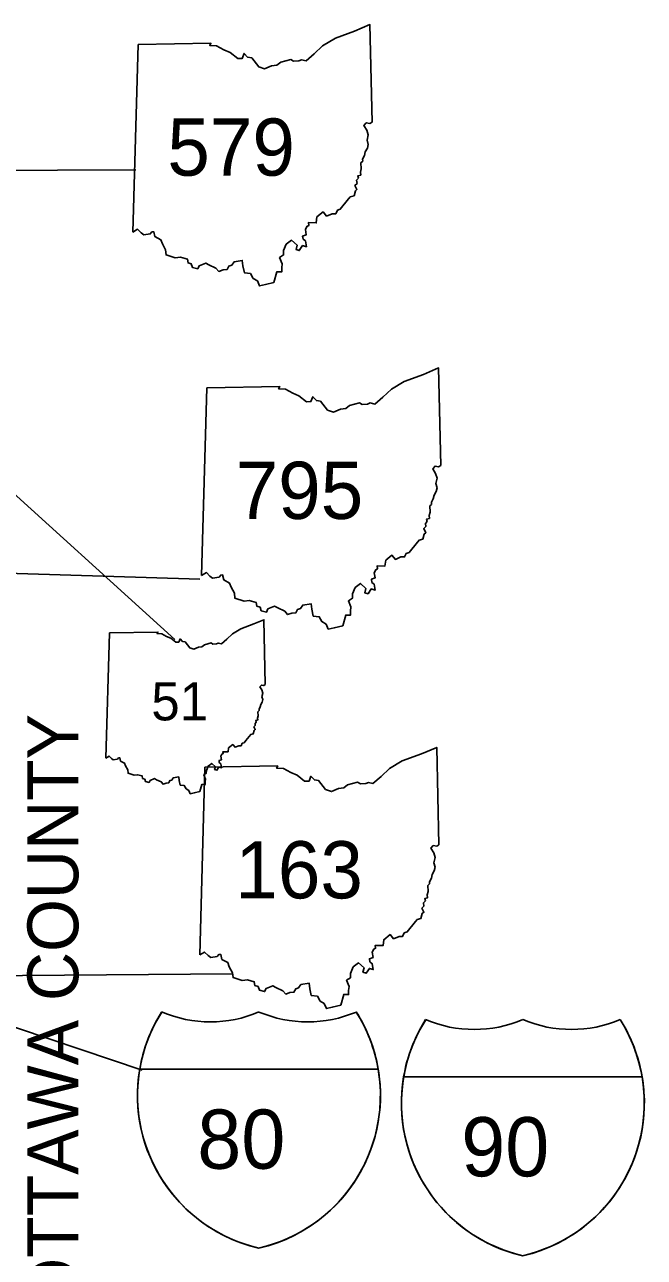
# Model space of a CAD drawing. Extents: x 0 to 851, y 0 to 440.
# Drawn here: x 425.3 to 466.1, y 277.3 to 358.6 of the extents above; entities that cross this region are included whole.
import ezdxf

# ---------------------------------------------------------------- set-up
doc = ezdxf.new("R2010")
doc.units = 0
for name, color, linetype in [('GM_X_Adjacent_County_Text', 7, 'Continuous'), ('GM_X_Interstate_Route', 7, 'Continuous'), ('GM_X_State_Route', 7, 'Continuous'), ('PV_P_Text', 7, 'Continuous')]:
    doc.layers.add(name, color=color, linetype=linetype)

msp = doc.modelspace()

# ---------------------------------------------------------------- linework, layer by layer
at = {"layer": 'GM_X_Interstate_Route'}
msp.add_lwpolyline([(422.811, 293.104), (433.003, 289.671)], dxfattribs=at)
at = {"layer": 'GM_X_State_Route'}
for points in [[(405.522, 348.977), (410.58, 348.972), (411.303, 348.959), (411.878, 348.96), (413.295, 348.968), (414.081, 348.964), (414.459, 348.972), (414.805, 348.979), (415.504, 348.964), (416.351, 348.962), (416.522, 348.963), (417.074, 348.966), (417.881, 348.962), (418.577, 348.966), (418.918, 348.962), (419.177, 348.959), (419.946, 348.952), (420.653, 348.95), (421.433, 348.96), (422.23, 348.953), (432.582, 349.009)], [(435.156, 318.06), (422.587, 329.422)], [(414.918, 322.727), (415.001, 322.725), (416.011, 322.704), (416.997, 322.68), (417.837, 322.648), (418.91, 322.624), (419.627, 322.596), (420.185, 322.567), (420.787, 322.544), (421.903, 322.491), (436.8, 322.031)], [(418.043, 295.878), (419.56, 295.875), (438.954, 296.017)]]:
    msp.add_lwpolyline(points, dxfattribs=at)
at = {"layer": 'PV_P_Text'}
for p, q in [((432.38, 344.897), (432.726, 357.27)), ((432.38, 344.897), (432.726, 357.27)), ((436.912, 322.277), (437.259, 334.649)), ((436.912, 322.277), (437.259, 334.649)), ((430.601, 310.244), (430.832, 318.493)), ((430.601, 310.244), (430.832, 318.493)), ((436.787, 297.273), (437.134, 309.645)), ((436.787, 297.273), (437.134, 309.645)), ((432.835, 289.738), (448.551, 289.738)), ((448.551, 289.738), (432.835, 289.738)), ((448.551, 289.738), (432.835, 289.738)), ((450.229, 289.236), (465.944, 289.236)), ((465.944, 289.236), (450.229, 289.236)), ((465.944, 289.236), (450.229, 289.236))]:
    msp.add_line(p, q, dxfattribs=at)
for points in [[(432.726, 357.27), (437.526, 357.351), (437.451, 357.201), (437.904, 357.17), (438.385, 356.905), (438.792, 356.738), (439.29, 356.345), (439.588, 356.349), (439.714, 356.672), (439.942, 356.423), (440.213, 356.379), (440.681, 355.786), (441.067, 355.658), (441.53, 355.861), (441.876, 355.894), (442.128, 356.095), (442.787, 356.267), (442.971, 356.164), (443.319, 356.185), (443.495, 356.26), (443.799, 356.193), (444.335, 356.642), (444.886, 357.173), (445.734, 357.673), (447, 358.148), (448.001, 358.572), (448.146, 352.151)], [(432.726, 357.27), (437.526, 357.351), (437.451, 357.201), (437.904, 357.17), (438.385, 356.905), (438.792, 356.738), (439.29, 356.345), (439.588, 356.349), (439.714, 356.672), (439.942, 356.423), (440.213, 356.379), (440.681, 355.786), (441.067, 355.658), (441.53, 355.861), (441.876, 355.894), (442.128, 356.095), (442.787, 356.267), (442.971, 356.164), (443.319, 356.185), (443.495, 356.26), (443.799, 356.193), (444.335, 356.642), (444.886, 357.173), (445.734, 357.673), (447, 358.148), (448.001, 358.572), (448.146, 352.151)], [(448.146, 352.151), (447.998, 352.061), (447.768, 352.103), (447.613, 351.923), (447.805, 351.623), (447.895, 351.305), (447.815, 350.956), (447.894, 350.667), (447.84, 350.425), (447.696, 350.185), (447.646, 349.956), (447.523, 349.714), (447.533, 349.579), (447.416, 349.472), (447.437, 349.071), (447.378, 348.848), (447.398, 348.656), (447.208, 348.606), (447.252, 348.447), (447.131, 348.325), (447.157, 348.114), (447.02, 347.98), (447.153, 347.71), (447.046, 347.625), (446.957, 347.297), (446.713, 347.231), (446.225, 346.631), (446.053, 346.405), (445.859, 346.349), (445.753, 346.116), (445.515, 346.115), (445.154, 345.954), (444.921, 346.231), (444.512, 345.897), (444.465, 345.512), (443.949, 345.524), (443.969, 345.329), (443.854, 345.272), (443.749, 345.077), (443.81, 344.729), (443.568, 344.641), (443.597, 344.439), (443.752, 344.316), (443.821, 343.931), (443.564, 344.009), (443.353, 343.684), (443.137, 343.76), (443.208, 344.035), (442.842, 344.366), (442.496, 344.101), (442.316, 343.678), (442.314, 343.393), (442.056, 343.221), (442.221, 342.819), (442.191, 342.541), (442.196, 342.278), (441.874, 342.288), (441.679, 341.577)], [(448.146, 352.151), (447.998, 352.061), (447.768, 352.103), (447.613, 351.923), (447.805, 351.623), (447.895, 351.305), (447.815, 350.956), (447.894, 350.667), (447.84, 350.425), (447.696, 350.185), (447.646, 349.956), (447.523, 349.714), (447.533, 349.579), (447.416, 349.472), (447.437, 349.071), (447.378, 348.848), (447.398, 348.656), (447.208, 348.606), (447.252, 348.447), (447.131, 348.325), (447.157, 348.114), (447.02, 347.98), (447.153, 347.71), (447.046, 347.625), (446.957, 347.297), (446.713, 347.231), (446.225, 346.631), (446.053, 346.405), (445.859, 346.349), (445.753, 346.116), (445.515, 346.115), (445.154, 345.954), (444.921, 346.231), (444.512, 345.897), (444.465, 345.512), (443.949, 345.524), (443.969, 345.329), (443.854, 345.272), (443.749, 345.077), (443.81, 344.729), (443.568, 344.641), (443.597, 344.439), (443.752, 344.316), (443.821, 343.931), (443.564, 344.009), (443.353, 343.684), (443.137, 343.76), (443.208, 344.035), (442.842, 344.366), (442.496, 344.101), (442.316, 343.678), (442.314, 343.393), (442.056, 343.221), (442.221, 342.819), (442.191, 342.541), (442.196, 342.278), (441.874, 342.288), (441.679, 341.577)], [(441.679, 341.577), (441.118, 341.441), (440.73, 341.36), (440.592, 341.683), (440.314, 341.853), (440.133, 342.178), (439.734, 342.222), (439.639, 342.668), (439.595, 343.03), (439.049, 342.941), (438.899, 342.72), (438.705, 342.66), (438.593, 342.437), (438.329, 342.418), (438.046, 342.313), (437.86, 342.532), (437.396, 342.752), (437.188, 342.865), (436.751, 342.689), (436.658, 342.481), (436.311, 342.572), (436.23, 342.805), (436.019, 342.874), (435.973, 343.121), (435.524, 343.252), (435.18, 343.2), (434.574, 343.398), (434.537, 343.722), (434.331, 344.118), (434.223, 344.392), (433.84, 344.601), (433.763, 344.928), (433.64, 344.918), (433.528, 344.786), (433.103, 344.725), (432.933, 344.858), (432.694, 345.086), (432.38, 344.897)], [(441.679, 341.577), (441.118, 341.441), (440.73, 341.36), (440.592, 341.683), (440.314, 341.853), (440.133, 342.178), (439.734, 342.222), (439.639, 342.668), (439.595, 343.03), (439.049, 342.941), (438.899, 342.72), (438.705, 342.66), (438.593, 342.437), (438.329, 342.418), (438.046, 342.313), (437.86, 342.532), (437.396, 342.752), (437.188, 342.865), (436.751, 342.689), (436.658, 342.481), (436.311, 342.572), (436.23, 342.805), (436.019, 342.874), (435.973, 343.121), (435.524, 343.252), (435.18, 343.2), (434.574, 343.398), (434.537, 343.722), (434.331, 344.118), (434.223, 344.392), (433.84, 344.601), (433.763, 344.928), (433.64, 344.918), (433.528, 344.786), (433.103, 344.725), (432.933, 344.858), (432.694, 345.086), (432.38, 344.897)], [(437.259, 334.649), (442.059, 334.73), (441.984, 334.58), (442.437, 334.549), (442.918, 334.285), (443.325, 334.118), (443.823, 333.725), (444.121, 333.729), (444.247, 334.051), (444.475, 333.803), (444.746, 333.758), (445.213, 333.166), (445.6, 333.038), (446.062, 333.241), (446.408, 333.274), (446.661, 333.475), (447.32, 333.646), (447.504, 333.543), (447.852, 333.564), (448.028, 333.64), (448.332, 333.572), (448.867, 334.022), (449.419, 334.553), (450.266, 335.053), (451.533, 335.527), (452.534, 335.951), (452.679, 329.531)], [(437.259, 334.649), (442.059, 334.73), (441.984, 334.58), (442.437, 334.549), (442.918, 334.285), (443.325, 334.118), (443.823, 333.725), (444.121, 333.729), (444.247, 334.051), (444.475, 333.803), (444.746, 333.758), (445.213, 333.166), (445.6, 333.038), (446.062, 333.241), (446.408, 333.274), (446.661, 333.475), (447.32, 333.646), (447.504, 333.543), (447.852, 333.564), (448.028, 333.64), (448.332, 333.572), (448.867, 334.022), (449.419, 334.553), (450.266, 335.053), (451.533, 335.527), (452.534, 335.951), (452.679, 329.531)], [(452.679, 329.531), (452.531, 329.441), (452.301, 329.483), (452.146, 329.303), (452.338, 329.002), (452.428, 328.685), (452.348, 328.335), (452.427, 328.046), (452.373, 327.805), (452.229, 327.565), (452.179, 327.335), (452.056, 327.094), (452.066, 326.959), (451.949, 326.852), (451.97, 326.45), (451.911, 326.228), (451.931, 326.036), (451.741, 325.986), (451.785, 325.827), (451.664, 325.705), (451.69, 325.494), (451.553, 325.359), (451.686, 325.09), (451.579, 325.004), (451.49, 324.677), (451.246, 324.61), (450.758, 324.011), (450.586, 323.785), (450.392, 323.728), (450.286, 323.495), (450.047, 323.495), (449.687, 323.334), (449.454, 323.611), (449.045, 323.277), (448.998, 322.891), (448.482, 322.904), (448.502, 322.708), (448.387, 322.652), (448.282, 322.456), (448.343, 322.109), (448.101, 322.021), (448.13, 321.819), (448.285, 321.695), (448.354, 321.31), (448.097, 321.388), (447.886, 321.064), (447.67, 321.14), (447.741, 321.415), (447.375, 321.746), (447.029, 321.481), (446.849, 321.057), (446.847, 320.773), (446.589, 320.6), (446.754, 320.198), (446.724, 319.921), (446.729, 319.658), (446.407, 319.667), (446.211, 318.957)], [(452.679, 329.531), (452.531, 329.441), (452.301, 329.483), (452.146, 329.303), (452.338, 329.002), (452.428, 328.685), (452.348, 328.335), (452.427, 328.046), (452.373, 327.805), (452.229, 327.565), (452.179, 327.335), (452.056, 327.094), (452.066, 326.959), (451.949, 326.852), (451.97, 326.45), (451.911, 326.228), (451.931, 326.036), (451.741, 325.986), (451.785, 325.827), (451.664, 325.705), (451.69, 325.494), (451.553, 325.359), (451.686, 325.09), (451.579, 325.004), (451.49, 324.677), (451.246, 324.61), (450.758, 324.011), (450.586, 323.785), (450.392, 323.728), (450.286, 323.495), (450.047, 323.495), (449.687, 323.334), (449.454, 323.611), (449.045, 323.277), (448.998, 322.891), (448.482, 322.904), (448.502, 322.708), (448.387, 322.652), (448.282, 322.456), (448.343, 322.109), (448.101, 322.021), (448.13, 321.819), (448.285, 321.695), (448.354, 321.31), (448.097, 321.388), (447.886, 321.064), (447.67, 321.14), (447.741, 321.415), (447.375, 321.746), (447.029, 321.481), (446.849, 321.057), (446.847, 320.773), (446.589, 320.6), (446.754, 320.198), (446.724, 319.921), (446.729, 319.658), (446.407, 319.667), (446.211, 318.957)], [(446.211, 318.957), (445.651, 318.821), (445.263, 318.74), (445.125, 319.062), (444.847, 319.232), (444.666, 319.557), (444.267, 319.602), (444.172, 320.048), (444.128, 320.41), (443.582, 320.32), (443.432, 320.099), (443.238, 320.04), (443.126, 319.817), (442.862, 319.798), (442.579, 319.693), (442.393, 319.911), (441.929, 320.131), (441.721, 320.244), (441.284, 320.068), (441.191, 319.86), (440.844, 319.952), (440.763, 320.184), (440.552, 320.254), (440.506, 320.5), (440.057, 320.632), (439.713, 320.58), (439.107, 320.778), (439.07, 321.102), (438.864, 321.497), (438.756, 321.772), (438.373, 321.981), (438.296, 322.307), (438.173, 322.297), (438.061, 322.165), (437.635, 322.104), (437.465, 322.238), (437.227, 322.465), (436.912, 322.277)], [(446.211, 318.957), (445.651, 318.821), (445.263, 318.74), (445.125, 319.062), (444.847, 319.232), (444.666, 319.557), (444.267, 319.602), (444.172, 320.048), (444.128, 320.41), (443.582, 320.32), (443.432, 320.099), (443.238, 320.04), (443.126, 319.817), (442.862, 319.798), (442.579, 319.693), (442.393, 319.911), (441.929, 320.131), (441.721, 320.244), (441.284, 320.068), (441.191, 319.86), (440.844, 319.952), (440.763, 320.184), (440.552, 320.254), (440.506, 320.5), (440.057, 320.632), (439.713, 320.58), (439.107, 320.778), (439.07, 321.102), (438.864, 321.497), (438.756, 321.772), (438.373, 321.981), (438.296, 322.307), (438.173, 322.297), (438.061, 322.165), (437.635, 322.104), (437.465, 322.238), (437.227, 322.465), (436.912, 322.277)], [(430.832, 318.493), (434.032, 318.546), (433.982, 318.447), (434.284, 318.426), (434.605, 318.249), (434.876, 318.138), (435.208, 317.876), (435.407, 317.879), (435.49, 318.094), (435.643, 317.928), (435.823, 317.898), (436.135, 317.504), (436.393, 317.418), (436.701, 317.553), (436.932, 317.576), (437.1, 317.709), (437.539, 317.824), (437.662, 317.755), (437.894, 317.769), (438.011, 317.82), (438.214, 317.774), (438.571, 318.074), (438.938, 318.428), (439.504, 318.762), (440.348, 319.078), (441.015, 319.36), (441.112, 315.08)], [(430.832, 318.493), (434.032, 318.546), (433.982, 318.447), (434.284, 318.426), (434.605, 318.249), (434.876, 318.138), (435.208, 317.876), (435.407, 317.879), (435.49, 318.094), (435.643, 317.928), (435.823, 317.898), (436.135, 317.504), (436.393, 317.418), (436.701, 317.553), (436.932, 317.576), (437.1, 317.709), (437.539, 317.824), (437.662, 317.755), (437.894, 317.769), (438.011, 317.82), (438.214, 317.774), (438.571, 318.074), (438.938, 318.428), (439.504, 318.762), (440.348, 319.078), (441.015, 319.36), (441.112, 315.08)], [(441.112, 315.08), (441.013, 315.02), (440.86, 315.048), (440.757, 314.928), (440.884, 314.728), (440.945, 314.516), (440.891, 314.283), (440.944, 314.091), (440.908, 313.93), (440.812, 313.769), (440.778, 313.617), (440.697, 313.456), (440.703, 313.366), (440.625, 313.294), (440.639, 313.026), (440.6, 312.878), (440.613, 312.75), (440.487, 312.717), (440.516, 312.611), (440.435, 312.529), (440.452, 312.389), (440.361, 312.299), (440.45, 312.119), (440.378, 312.063), (440.319, 311.844), (440.157, 311.8), (439.831, 311.4), (439.716, 311.249), (439.587, 311.212), (439.516, 311.057), (439.358, 311.056), (439.117, 310.949), (438.962, 311.134), (438.689, 310.911), (438.658, 310.654), (438.314, 310.662), (438.327, 310.532), (438.25, 310.494), (438.18, 310.364), (438.221, 310.132), (438.06, 310.073), (438.079, 309.939), (438.183, 309.857), (438.228, 309.6), (438.057, 309.652), (437.917, 309.435), (437.773, 309.486), (437.82, 309.67), (437.576, 309.89), (437.345, 309.713), (437.225, 309.431), (437.224, 309.241), (437.052, 309.127), (437.162, 308.858), (437.142, 308.674), (437.145, 308.498), (436.93, 308.504), (436.8, 308.031)], [(441.112, 315.08), (441.013, 315.02), (440.86, 315.048), (440.757, 314.928), (440.884, 314.728), (440.945, 314.516), (440.891, 314.283), (440.944, 314.091), (440.908, 313.93), (440.812, 313.769), (440.778, 313.617), (440.697, 313.456), (440.703, 313.366), (440.625, 313.294), (440.639, 313.026), (440.6, 312.878), (440.613, 312.75), (440.487, 312.717), (440.516, 312.611), (440.435, 312.529), (440.452, 312.389), (440.361, 312.299), (440.45, 312.119), (440.378, 312.063), (440.319, 311.844), (440.157, 311.8), (439.831, 311.4), (439.716, 311.249), (439.587, 311.212), (439.516, 311.057), (439.358, 311.056), (439.117, 310.949), (438.962, 311.134), (438.689, 310.911), (438.658, 310.654), (438.314, 310.662), (438.327, 310.532), (438.25, 310.494), (438.18, 310.364), (438.221, 310.132), (438.06, 310.073), (438.079, 309.939), (438.183, 309.857), (438.228, 309.6), (438.057, 309.652), (437.917, 309.435), (437.773, 309.486), (437.82, 309.67), (437.576, 309.89), (437.345, 309.713), (437.225, 309.431), (437.224, 309.241), (437.052, 309.127), (437.162, 308.858), (437.142, 308.674), (437.145, 308.498), (436.93, 308.504), (436.8, 308.031)], [(436.8, 308.031), (436.427, 307.94), (436.168, 307.886), (436.076, 308.101), (435.891, 308.215), (435.77, 308.431), (435.504, 308.461), (435.441, 308.758), (435.411, 308.999), (435.047, 308.94), (434.947, 308.792), (434.818, 308.753), (434.743, 308.604), (434.567, 308.592), (434.378, 308.521), (434.255, 308.667), (433.945, 308.814), (433.806, 308.889), (433.515, 308.772), (433.453, 308.633), (433.222, 308.694), (433.168, 308.849), (433.028, 308.896), (432.997, 309.06), (432.697, 309.147), (432.468, 309.113), (432.064, 309.245), (432.04, 309.461), (431.902, 309.724), (431.83, 309.907), (431.575, 310.047), (431.523, 310.264), (431.441, 310.258), (431.367, 310.17), (431.083, 310.129), (430.97, 310.218), (430.811, 310.37), (430.601, 310.244)], [(436.8, 308.031), (436.427, 307.94), (436.168, 307.886), (436.076, 308.101), (435.891, 308.215), (435.77, 308.431), (435.504, 308.461), (435.441, 308.758), (435.411, 308.999), (435.047, 308.94), (434.947, 308.792), (434.818, 308.753), (434.743, 308.604), (434.567, 308.592), (434.378, 308.521), (434.255, 308.667), (433.945, 308.814), (433.806, 308.889), (433.515, 308.772), (433.453, 308.633), (433.222, 308.694), (433.168, 308.849), (433.028, 308.896), (432.997, 309.06), (432.697, 309.147), (432.468, 309.113), (432.064, 309.245), (432.04, 309.461), (431.902, 309.724), (431.83, 309.907), (431.575, 310.047), (431.523, 310.264), (431.441, 310.258), (431.367, 310.17), (431.083, 310.129), (430.97, 310.218), (430.811, 310.37), (430.601, 310.244)], [(437.134, 309.645), (441.934, 309.726), (441.859, 309.576), (442.312, 309.545), (442.793, 309.28), (443.2, 309.114), (443.698, 308.72), (443.996, 308.725), (444.122, 309.047), (444.35, 308.798), (444.62, 308.754), (445.088, 308.161), (445.475, 308.033), (445.937, 308.236), (446.283, 308.27), (446.536, 308.47), (447.195, 308.642), (447.379, 308.539), (447.727, 308.56), (447.903, 308.636), (448.207, 308.568), (448.742, 309.018), (449.294, 309.548), (450.141, 310.049), (451.408, 310.523), (452.409, 310.947), (452.554, 304.526)], [(437.134, 309.645), (441.934, 309.726), (441.859, 309.576), (442.312, 309.545), (442.793, 309.28), (443.2, 309.114), (443.698, 308.72), (443.996, 308.725), (444.122, 309.047), (444.35, 308.798), (444.62, 308.754), (445.088, 308.161), (445.475, 308.033), (445.937, 308.236), (446.283, 308.27), (446.536, 308.47), (447.195, 308.642), (447.379, 308.539), (447.727, 308.56), (447.903, 308.636), (448.207, 308.568), (448.742, 309.018), (449.294, 309.548), (450.141, 310.049), (451.408, 310.523), (452.409, 310.947), (452.554, 304.526)], [(452.554, 304.526), (452.406, 304.436), (452.176, 304.479), (452.021, 304.298), (452.213, 303.998), (452.303, 303.681), (452.223, 303.331), (452.302, 303.042), (452.248, 302.801), (452.104, 302.56), (452.054, 302.331), (451.931, 302.09), (451.941, 301.955), (451.824, 301.848), (451.845, 301.446), (451.786, 301.223), (451.806, 301.031), (451.616, 300.981), (451.66, 300.823), (451.539, 300.7), (451.565, 300.489), (451.428, 300.355), (451.561, 300.085), (451.454, 300), (451.365, 299.672), (451.121, 299.606), (450.633, 299.007), (450.461, 298.78), (450.267, 298.724), (450.161, 298.491), (449.922, 298.49), (449.562, 298.329), (449.329, 298.607), (448.92, 298.273), (448.873, 297.887), (448.357, 297.899), (448.377, 297.704), (448.262, 297.647), (448.157, 297.452), (448.218, 297.105), (447.976, 297.016), (448.005, 296.814), (448.16, 296.691), (448.229, 296.306), (447.972, 296.384), (447.761, 296.059), (447.545, 296.135), (447.616, 296.411), (447.25, 296.741), (446.904, 296.476), (446.724, 296.053), (446.722, 295.768), (446.464, 295.596), (446.629, 295.194), (446.599, 294.917), (446.604, 294.653), (446.282, 294.663), (446.086, 293.952)], [(452.554, 304.526), (452.406, 304.436), (452.176, 304.479), (452.021, 304.298), (452.213, 303.998), (452.303, 303.681), (452.223, 303.331), (452.302, 303.042), (452.248, 302.801), (452.104, 302.56), (452.054, 302.331), (451.931, 302.09), (451.941, 301.955), (451.824, 301.848), (451.845, 301.446), (451.786, 301.223), (451.806, 301.031), (451.616, 300.981), (451.66, 300.823), (451.539, 300.7), (451.565, 300.489), (451.428, 300.355), (451.561, 300.085), (451.454, 300), (451.365, 299.672), (451.121, 299.606), (450.633, 299.007), (450.461, 298.78), (450.267, 298.724), (450.161, 298.491), (449.922, 298.49), (449.562, 298.329), (449.329, 298.607), (448.92, 298.273), (448.873, 297.887), (448.357, 297.899), (448.377, 297.704), (448.262, 297.647), (448.157, 297.452), (448.218, 297.105), (447.976, 297.016), (448.005, 296.814), (448.16, 296.691), (448.229, 296.306), (447.972, 296.384), (447.761, 296.059), (447.545, 296.135), (447.616, 296.411), (447.25, 296.741), (446.904, 296.476), (446.724, 296.053), (446.722, 295.768), (446.464, 295.596), (446.629, 295.194), (446.599, 294.917), (446.604, 294.653), (446.282, 294.663), (446.086, 293.952)], [(446.086, 293.952), (445.526, 293.817), (445.137, 293.735), (445, 294.058), (444.722, 294.228), (444.541, 294.553), (444.142, 294.597), (444.047, 295.043), (444.003, 295.405), (443.457, 295.316), (443.307, 295.095), (443.113, 295.035), (443.001, 294.812), (442.737, 294.794), (442.454, 294.688), (442.268, 294.907), (441.804, 295.127), (441.596, 295.24), (441.159, 295.064), (441.066, 294.856), (440.719, 294.948), (440.637, 295.18), (440.427, 295.25), (440.381, 295.496), (439.932, 295.627), (439.588, 295.575), (438.982, 295.773), (438.945, 296.098), (438.739, 296.493), (438.631, 296.767), (438.248, 296.977), (438.17, 297.303), (438.048, 297.293), (437.936, 297.161), (437.51, 297.1), (437.34, 297.233), (437.102, 297.461), (436.787, 297.273)], [(446.086, 293.952), (445.526, 293.817), (445.137, 293.735), (445, 294.058), (444.722, 294.228), (444.541, 294.553), (444.142, 294.597), (444.047, 295.043), (444.003, 295.405), (443.457, 295.316), (443.307, 295.095), (443.113, 295.035), (443.001, 294.812), (442.737, 294.794), (442.454, 294.688), (442.268, 294.907), (441.804, 295.127), (441.596, 295.24), (441.159, 295.064), (441.066, 294.856), (440.719, 294.948), (440.637, 295.18), (440.427, 295.25), (440.381, 295.496), (439.932, 295.627), (439.588, 295.575), (438.982, 295.773), (438.945, 296.098), (438.739, 296.493), (438.631, 296.767), (438.248, 296.977), (438.17, 297.303), (438.048, 297.293), (437.936, 297.161), (437.51, 297.1), (437.34, 297.233), (437.102, 297.461), (436.787, 297.273)]]:
    msp.add_lwpolyline(points, dxfattribs=at)
for centre, radius, start, end in [((443.017, 288.007), 10.328, 147.82161, 256.99413), ((442.372, 288.186), 9.662, 146.65397, 170.75899), ((437.485, 301.099), 8.241, 247.08482, 292.91053), ((437.485, 301.099), 8.241, 247.08482, 292.91053), ((438.368, 288.007), 10.328, 283.00654, 32.17868), ((443.902, 301.1), 8.243, 247.09162, 292.90836), ((443.902, 301.1), 8.243, 247.09162, 292.90836), ((438.368, 288.007), 10.328, 9.64753, 32.17902), ((460.411, 287.505), 10.328, 147.82161, 256.99413), ((459.766, 287.684), 9.662, 146.65397, 170.75899), ((454.879, 300.596), 8.241, 247.08482, 292.91053), ((454.879, 300.596), 8.241, 247.08482, 292.91053), ((455.762, 287.505), 10.328, 283.00654, 32.17868), ((461.295, 300.598), 8.243, 247.09162, 292.90836), ((461.295, 300.598), 8.243, 247.09162, 292.90836), ((455.762, 287.505), 10.328, 9.64753, 32.17902), ((443.017, 288.007), 10.328, 170.35136, 256.9967), ((438.39, 288.003), 10.308, 282.76665, 9.68983), ((460.411, 287.505), 10.328, 170.35136, 256.9967), ((455.784, 287.501), 10.308, 282.76665, 9.68983)]:
    msp.add_arc(centre, radius, start, end, dxfattribs=at)

# ---------------------------------------------------------------- texts
at = {"layer": 'GM_X_Adjacent_County_Text'}
msp.add_text('OTTAWA COUNTY', height=3.35, rotation=90, dxfattribs=at).set_placement((428.785, 273.823))
at = {"layer": 'PV_P_Text'}
for s, height, p in [('579', 3.7688, (434.653, 348.619)), ('795', 3.7688, (439.156, 325.999)), ('51', 2.5126, (433.6, 312.725)), ('163', 3.7688, (439.135, 300.994)), ('80', 3.9007, (436.629, 283.179)), ('90', 3.9007, (454.023, 282.676))]:
    msp.add_text(s, height=height, dxfattribs=at).set_placement(p)

doc.saveas('drawing.dxf')
